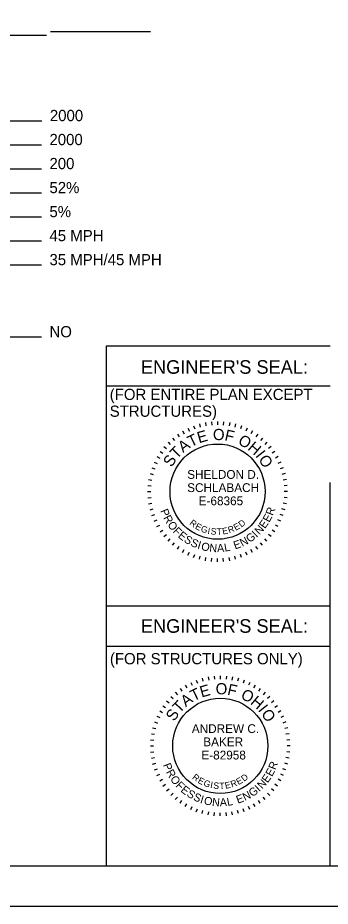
# Model space of a CAD drawing. Extents: x 0 to 40.9, y 0 to 22.
# Drawn here: x 7.34 to 11.25, y 0 to 11.1 of the extents above; entities that cross this region are included whole.
import ezdxf

# ---------------------------------------------------------------- set-up
doc = ezdxf.new("R2010")
doc.units = 0
for name, color, linetype in [('SH_Border', 7, 'Continuous'), ('SH_Cut_Line', 7, 'Continuous'), ('SH_Data', 7, 'Continuous'), ('SH_Text', 7, 'Continuous')]:
    doc.layers.add(name, color=color, linetype=linetype)

msp = doc.modelspace()

# ---------------------------------------------------------------- linework, layer by layer
at = {"layer": 'SH_Cut_Line'}
for p, q in [((7.7, 10.877), (3.347, 10.877)), ((9, 10.922), (7.75, 10.922)), ((7.642, 9.806), (3.871, 9.806)), ((7.637, 9.506), (4.189, 9.506)), ((7.637, 9.206), (4.872, 9.206)), ((7.637, 8.906), (4.604, 8.906)), ((7.637, 8.606), (4.189, 8.606)), ((7.637, 8.306), (3.346, 8.306)), ((7.637, 8.006), (3.242, 8.006)), ((7.637, 7.106), (3.267, 7.106)), ((8.45, 3.75), (8.45, 7)), ((8.45, 7), (11.25, 7)), ((8.45, 6.5), (11.25, 6.5)), ((9.54, 6), (9.554, 5.963)), ((9.613, 6.023), (9.624, 5.985)), ((9.688, 6.04), (9.695, 6)), ((9.763, 6.05), (9.767, 6.01)), ((9.84, 6.053), (9.84, 6.013)), ((9.916, 6.05), (9.912, 6.01)), ((9.992, 6.04), (9.985, 6)), ((10.066, 6.023), (10.056, 5.985)), ((10.139, 6), (10.125, 5.963)), ((9.338, 5.895), (9.361, 5.862)), ((9.402, 5.936), (9.422, 5.901)), ((9.47, 5.971), (9.487, 5.935)), ((10.209, 5.971), (10.193, 5.935)), ((10.277, 5.936), (10.257, 5.901)), ((10.342, 5.895), (10.319, 5.862)), ((9.221, 5.797), (9.249, 5.769)), ((9.277, 5.848), (9.303, 5.818)), ((10.402, 5.848), (10.376, 5.818)), ((10.458, 5.797), (10.43, 5.769)), ((9.123, 5.68), (9.156, 5.657)), ((9.169, 5.741), (9.2, 5.715)), ((10.51, 5.741), (10.479, 5.715)), ((10.556, 5.68), (10.524, 5.657)), ((9.082, 5.616), (9.117, 5.596)), ((10.597, 5.616), (10.563, 5.596)), ((9.017, 5.477), (9.055, 5.464)), ((9.047, 5.548), (9.083, 5.531)), ((10.633, 5.548), (10.596, 5.531)), ((10.662, 5.477), (10.624, 5.464)), ((8.978, 5.33), (9.017, 5.323)), ((8.995, 5.405), (9.033, 5.394)), ((10.685, 5.405), (10.646, 5.394)), ((10.701, 5.33), (10.662, 5.323)), ((8.968, 5.254), (9.008, 5.251)), ((10.711, 5.254), (10.672, 5.251)), ((11.25, 0.5), (11.25, 5.292)), ((8.965, 5.178), (9.005, 5.178)), ((8.968, 5.102), (9.008, 5.105)), ((10.711, 5.102), (10.672, 5.105)), ((10.715, 5.178), (10.675, 5.178)), ((8.978, 5.026), (9.017, 5.033)), ((10.701, 5.026), (10.662, 5.033)), ((8.995, 4.952), (9.033, 4.962)), ((9.017, 4.879), (9.055, 4.893)), ((10.662, 4.879), (10.624, 4.893)), ((10.685, 4.952), (10.646, 4.962)), ((9.047, 4.808), (9.083, 4.825)), ((10.633, 4.808), (10.596, 4.825)), ((9.082, 4.741), (9.117, 4.761)), ((9.123, 4.676), (9.156, 4.699)), ((10.556, 4.676), (10.524, 4.699)), ((10.597, 4.741), (10.563, 4.761)), ((9.169, 4.616), (9.2, 4.641)), ((9.221, 4.559), (9.249, 4.588)), ((10.458, 4.559), (10.43, 4.588)), ((10.51, 4.616), (10.479, 4.641)), ((9.277, 4.508), (9.303, 4.539)), ((9.338, 4.461), (9.361, 4.494)), ((9.402, 4.42), (9.422, 4.455)), ((10.277, 4.42), (10.257, 4.455)), ((10.342, 4.461), (10.319, 4.494)), ((10.402, 4.508), (10.376, 4.539)), ((9.47, 4.385), (9.487, 4.421)), ((9.54, 4.356), (9.554, 4.394)), ((9.613, 4.333), (9.624, 4.372)), ((9.688, 4.316), (9.695, 4.356)), ((9.763, 4.307), (9.767, 4.346)), ((9.84, 4.303), (9.84, 4.343)), ((9.916, 4.307), (9.912, 4.346)), ((9.992, 4.316), (9.985, 4.356)), ((10.066, 4.333), (10.056, 4.372)), ((10.139, 4.356), (10.125, 4.394)), ((10.209, 4.385), (10.193, 4.421)), ((8.45, 0.5), (8.45, 3.75)), ((8.45, 3.75), (11.25, 3.75)), ((8.45, 3.25), (11.25, 3.25)), ((9.504, 2.796), (9.521, 2.76)), ((9.574, 2.825), (9.588, 2.787)), ((9.647, 2.848), (9.657, 2.809)), ((9.722, 2.864), (9.729, 2.825)), ((9.797, 2.874), (9.801, 2.835)), ((9.874, 2.878), (9.874, 2.838)), ((9.95, 2.874), (9.946, 2.835)), ((10.025, 2.864), (10.019, 2.825)), ((10.1, 2.848), (10.09, 2.809)), ((10.173, 2.825), (10.159, 2.787)), ((10.243, 2.796), (10.226, 2.76)), ((9.311, 2.673), (9.337, 2.642)), ((9.372, 2.719), (9.395, 2.687)), ((9.436, 2.761), (9.456, 2.726)), ((10.311, 2.761), (10.291, 2.726)), ((10.375, 2.719), (10.352, 2.687)), ((10.436, 2.673), (10.41, 2.642)), ((9.203, 2.565), (9.234, 2.539)), ((9.255, 2.621), (9.283, 2.593)), ((10.492, 2.621), (10.464, 2.593)), ((10.544, 2.565), (10.513, 2.539)), ((9.157, 2.505), (9.19, 2.482)), ((10.59, 2.505), (10.558, 2.482)), ((9.081, 2.373), (9.117, 2.356)), ((9.116, 2.44), (9.15, 2.42)), ((10.631, 2.44), (10.597, 2.42)), ((10.667, 2.373), (10.63, 2.356)), ((9.028, 2.229), (9.067, 2.219)), ((9.051, 2.302), (9.089, 2.288)), ((10.696, 2.302), (10.658, 2.288)), ((10.719, 2.229), (10.68, 2.219)), ((9.012, 2.155), (9.051, 2.148)), ((10.735, 2.155), (10.696, 2.148)), ((8.999, 2.003), (9.039, 2.003)), ((9.002, 2.079), (9.042, 2.076)), ((10.745, 2.079), (10.705, 2.076)), ((10.749, 2.003), (10.709, 2.003)), ((9.002, 1.926), (9.042, 1.93)), ((10.745, 1.926), (10.705, 1.93)), ((9.012, 1.851), (9.051, 1.858)), ((9.028, 1.776), (9.067, 1.787)), ((10.719, 1.776), (10.68, 1.787)), ((10.735, 1.851), (10.696, 1.858)), ((9.051, 1.703), (9.089, 1.717)), ((10.696, 1.703), (10.658, 1.717)), ((9.081, 1.633), (9.117, 1.65)), ((9.116, 1.565), (9.15, 1.585)), ((10.631, 1.565), (10.597, 1.585)), ((10.667, 1.633), (10.63, 1.65)), ((9.157, 1.501), (9.19, 1.524)), ((9.203, 1.44), (9.234, 1.466)), ((10.544, 1.44), (10.513, 1.466)), ((10.59, 1.501), (10.558, 1.524)), ((9.255, 1.384), (9.283, 1.412)), ((9.311, 1.332), (9.337, 1.363)), ((10.436, 1.332), (10.41, 1.363)), ((10.492, 1.384), (10.464, 1.412)), ((9.372, 1.286), (9.395, 1.319)), ((9.436, 1.245), (9.456, 1.28)), ((9.504, 1.21), (9.521, 1.246)), ((10.243, 1.21), (10.226, 1.246)), ((10.311, 1.245), (10.291, 1.28)), ((10.375, 1.286), (10.352, 1.319)), ((9.574, 1.181), (9.588, 1.218)), ((9.647, 1.158), (9.657, 1.196)), ((9.722, 1.141), (9.729, 1.18)), ((9.797, 1.131), (9.801, 1.171)), ((9.874, 1.128), (9.874, 1.168)), ((9.95, 1.131), (9.946, 1.171)), ((10.025, 1.141), (10.019, 1.18)), ((10.1, 1.158), (10.09, 1.196)), ((10.173, 1.181), (10.159, 1.218))]:
    msp.add_line(p, q, dxfattribs=at)
for centre in [(9.84, 5.178), (9.874, 2.003)]:
    msp.add_circle(centre, 0.595, dxfattribs=at)
at = {"layer": 'SH_Data'}
msp.add_lwpolyline([(0, 0), (34, 0), (34, 22), (0, 22)], close=True, dxfattribs=at)
at = {"layer": 'SH_Text'}
msp.add_lwpolyline([(1.5, 21.5), (33.5, 21.5), (33.5, 0.5), (1.5, 0.5)], close=True, dxfattribs=at)

# ---------------------------------------------------------------- texts
at = {"layer": 'SH_Border'}
for s, height, p in [('2000', 0.14, (7.742, 9.806)), ('2000', 0.14, (7.737, 9.506)), ('200', 0.14, (7.737, 9.206)), ('52%', 0.14, (7.737, 8.906)), ('5%', 0.14, (7.737, 8.606)), ('45 MPH', 0.14, (7.737, 8.306)), ('35 MPH/45 MPH', 0.14, (7.737, 8.006)), ('NO', 0.14, (7.737, 7.106)), ("ENGINEER'S SEAL:", 0.17, (8.881, 6.65)), ('(FOR ENTIRE PLAN EXCEPT ', 0.14, (8.491, 6.323)), ('STRUCTURES)', 0.14, (8.491, 6.113)), ("ENGINEER'S SEAL:", 0.17, (8.881, 3.415)), ('(FOR STRUCTURES ONLY)', 0.14, (8.493, 3.022))]:
    msp.add_text(s, height=height, dxfattribs=at).set_placement(p)
at = {"layer": 'SH_Cut_Line'}
for s, height, rotation, p in [('T', 0.14, 25.7167, (9.506, 5.732)), ('E', 0.14, 15.7571, (9.607, 5.782)), ('O', 0.14, 359.7812, (9.782, 5.822)), ('F', 0.14, 347.4362, (9.921, 5.82)), ('O', 0.14, 332.2586, (10.086, 5.776)), ('A', 0.14, 36.4747, (9.408, 5.66)), ('H', 0.14, 319.9136, (10.208, 5.71)), ('T', 0.14, 46.4344, (9.331, 5.578)), ('I', 0.14, 308.367, (10.307, 5.625)), ('S', 0.14, 57.1924, (9.266, 5.476)), ('O', 0.14, 303.1491, (10.346, 5.581)), ('P', 0.1, 291.494, (9.122, 4.94)), ('R', 0.1, 298.7311, (9.158, 4.852)), ('E', 0.1, 61.9951, (10.487, 4.787)), ('R', 0.1, 69.2322, (10.531, 4.872)), ('O', 0.1, 306.4666, (9.208, 4.763)), ('R', 0.08, 323.2378, (9.482, 4.772)), ('E', 0.08, 332.4256, (9.552, 4.72)), ('E', 0.08, 29.4558, (10.067, 4.688)), ('D', 0.08, 38.0378, (10.138, 4.727)), ('E', 0.1, 54.758, (10.432, 4.709)), ('F', 0.1, 314.7068, (9.274, 4.676)), ('E', 0.1, 321.4393, (9.337, 4.614)), ('G', 0.08, 341.0076, (9.623, 4.683)), ('I', 0.08, 350.8085, (9.711, 4.653)), ('S', 0.08, 355.1352, (9.751, 4.645)), ('T', 0.08, 3.7172, (9.832, 4.638)), ('E', 0.08, 11.686, (9.907, 4.642)), ('R', 0.08, 20.268, (9.986, 4.658)), ('I', 0.1, 43.287, (10.327, 4.6)), ('N', 0.1, 47.0224, (10.364, 4.633)), ('S', 0.1, 328.6764, (9.412, 4.555)), ('S', 0.1, 335.9134, (9.494, 4.506)), ('I', 0.1, 343.1505, (9.581, 4.468)), ('E', 0.1, 20.0742, (10.06, 4.455)), ('N', 0.1, 27.3113, (10.149, 4.488)), ('G', 0.1, 35.0469, (10.239, 4.536)), ('O', 0.1, 346.8859, (9.628, 4.452)), ('N', 0.1, 355.1261, (9.734, 4.429)), ('A', 0.1, 2.8617, (9.836, 4.422)), ('L', 0.1, 10.0987, (9.931, 4.428)), ('O', 0.14, 359.7812, (9.816, 2.647)), ('F', 0.14, 347.4362, (9.955, 2.644)), ('T', 0.14, 25.7167, (9.54, 2.557)), ('E', 0.14, 15.7571, (9.64, 2.606)), ('O', 0.14, 332.2586, (10.12, 2.601)), ('T', 0.14, 46.4344, (9.365, 2.403)), ('A', 0.14, 36.4747, (9.442, 2.485)), ('H', 0.14, 319.9136, (10.242, 2.534)), ('S', 0.14, 57.1924, (9.299, 2.301)), ('I', 0.14, 308.367, (10.341, 2.45)), ('O', 0.14, 303.1491, (10.38, 2.406)), ('P', 0.1, 291.494, (9.156, 1.765)), ('R', 0.1, 69.2322, (10.565, 1.696)), ('R', 0.1, 298.7311, (9.192, 1.676)), ('E', 0.1, 61.9951, (10.521, 1.612)), ('O', 0.1, 306.4666, (9.242, 1.587)), ('F', 0.1, 314.7068, (9.308, 1.501)), ('R', 0.08, 323.2378, (9.516, 1.597)), ('E', 0.08, 332.4256, (9.586, 1.545)), ('G', 0.08, 341.0076, (9.657, 1.507)), ('I', 0.08, 350.8085, (9.745, 1.478)), ('E', 0.08, 11.686, (9.94, 1.466)), ('R', 0.08, 20.268, (10.02, 1.482)), ('E', 0.08, 29.4558, (10.101, 1.512)), ('D', 0.08, 38.0378, (10.172, 1.552)), ('N', 0.1, 47.0224, (10.398, 1.458)), ('E', 0.1, 54.758, (10.466, 1.533)), ('E', 0.1, 321.4393, (9.371, 1.438)), ('S', 0.1, 328.6764, (9.446, 1.379)), ('S', 0.08, 355.1352, (9.785, 1.469)), ('T', 0.08, 3.7172, (9.865, 1.462)), ('G', 0.1, 35.0469, (10.273, 1.361)), ('I', 0.1, 43.287, (10.361, 1.425)), ('S', 0.1, 335.9134, (9.528, 1.33)), ('I', 0.1, 343.1505, (9.615, 1.292)), ('O', 0.1, 346.8859, (9.662, 1.277)), ('N', 0.1, 355.1261, (9.768, 1.254)), ('A', 0.1, 2.8617, (9.87, 1.247)), ('L', 0.1, 10.0987, (9.965, 1.252)), ('E', 0.1, 20.0742, (10.094, 1.279)), ('N', 0.1, 27.3113, (10.183, 1.313))]:
    msp.add_text(s, height=height, rotation=rotation, dxfattribs=at).set_placement(p)
for s, p in [('SHELDON D.', (9.46, 5.338)), ('SCHLABACH', (9.46, 5.173)), ('E-68365', (9.604, 5.008)), ('ANDREW C.', (9.518, 2.163)), ('BAKER', (9.661, 1.998)), ('E-82958', (9.638, 1.833))]:
    msp.add_text(s, height=0.11, dxfattribs=at).set_placement(p)

doc.saveas('drawing.dxf')
